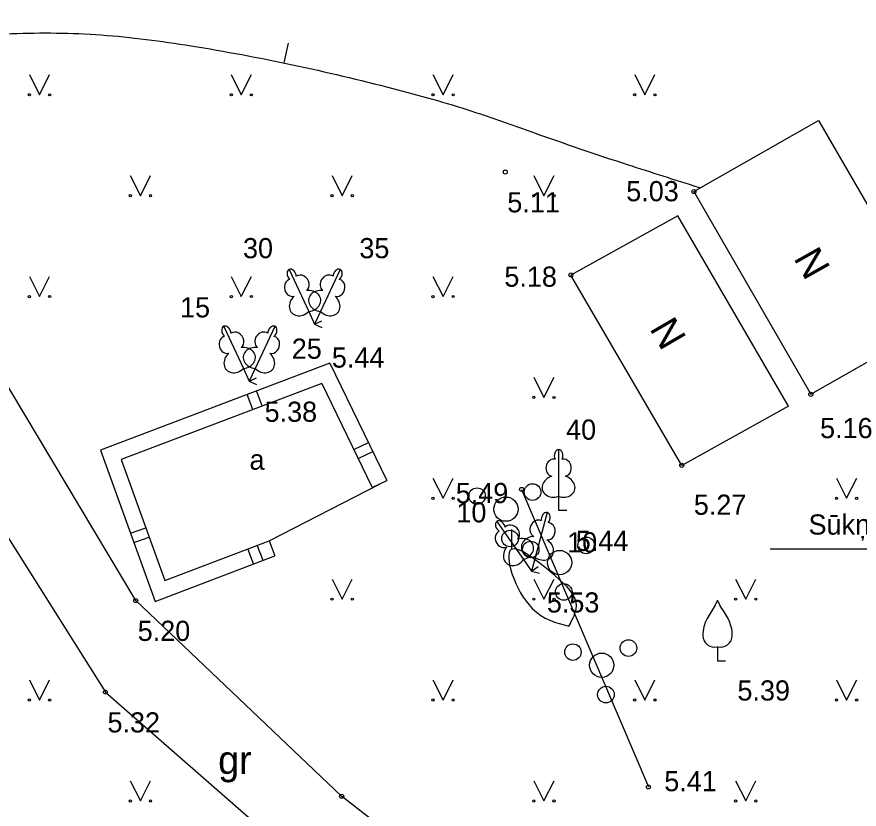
# Model space of a CAD drawing. Extents: x 519536 to 519949, y 326041 to 326519.
# Drawn here: x 519709.44 to 519730.31, y 326152.3 to 326171.93 of the extents above; entities that cross this region are included whole.
import ezdxf

# ---------------------------------------------------------------- set-up
doc = ezdxf.new("R2010")
doc.units = 0
for name, color, linetype in [('BUVE_BDET_####_####_#', 7, 'Continuous'), ('BUVE_BDET_####_TKST_#', 7, 'Continuous'), ('BUVE_EKAS_BPAL_####_#', 7, 'Continuous'), ('BUVE_EKAS_RAKS_TKST_#', 7, 'Continuous'), ('CELI_CMAL_####_####_#', 7, 'Continuous'), ('CELI_CSEG_####_TKST_#', 7, 'Continuous'), ('RELJ_AATZ_####_TKST_#', 7, 'Continuous'), ('RELJ_ELEM_####_####_#', 7, 'Continuous'), ('RELJ_HORZ_PAMT_####_#', 7, 'Continuous'), ('SKAN_ELEM_SPDK_TKST_#', 7, 'Continuous'), ('TERT_DIAM_####_TKST_#', 7, 'Continuous'), ('TERT_ELEM_####_####_#', 7, 'Continuous'), ('TERT_KRND_####_####_#', 7, 'Continuous')]:
    doc.layers.add(name, color=color, linetype=linetype)

msp = doc.modelspace()

# ---------------------------------------------------------------- linework, layer by layer
at = {"layer": 'BUVE_BDET_####_####_#'}
for p, q in [((519717.197, 326163.352), (519711.51, 326161.196)), ((519717.197, 326163.352), (519711.51, 326161.196)), ((519717.197, 326163.352), (519711.51, 326161.196)), ((519717.197, 326163.352), (519711.51, 326161.196)), ((519717.197, 326163.352), (519711.51, 326161.196)), ((519717.197, 326163.352), (519711.51, 326161.196)), ((519717.197, 326163.352), (519711.51, 326161.196)), ((519717.197, 326163.352), (519711.51, 326161.196)), ((519717.197, 326163.352), (519711.51, 326161.196)), ((519717.197, 326163.352), (519711.51, 326161.196)), ((519717.197, 326163.352), (519711.51, 326161.196)), ((519717.197, 326163.352), (519711.51, 326161.196)), ((519717.197, 326163.352), (519718.607, 326160.441)), ((519717.197, 326163.352), (519718.607, 326160.441)), ((519717.197, 326163.352), (519718.607, 326160.441)), ((519717.197, 326163.352), (519718.607, 326160.441)), ((519717.197, 326163.352), (519718.607, 326160.441)), ((519717.197, 326163.352), (519718.607, 326160.441)), ((519717.197, 326163.352), (519718.607, 326160.441)), ((519717.197, 326163.352), (519718.607, 326160.441)), ((519717.197, 326163.352), (519718.607, 326160.441)), ((519717.197, 326163.352), (519718.607, 326160.441)), ((519717.197, 326163.352), (519718.607, 326160.441)), ((519717.197, 326163.352), (519718.607, 326160.441)), ((519716.997, 326162.849), (519712.02, 326160.962)), ((519716.997, 326162.849), (519712.02, 326160.962)), ((519716.997, 326162.849), (519712.02, 326160.962)), ((519716.997, 326162.849), (519712.02, 326160.962)), ((519716.997, 326162.849), (519712.02, 326160.962)), ((519716.997, 326162.849), (519712.02, 326160.962)), ((519716.997, 326162.849), (519712.02, 326160.962)), ((519716.997, 326162.849), (519712.02, 326160.962)), ((519716.997, 326162.849), (519712.02, 326160.962)), ((519716.997, 326162.849), (519712.02, 326160.962)), ((519716.997, 326162.849), (519712.02, 326160.962)), ((519716.997, 326162.849), (519712.02, 326160.962)), ((519716.997, 326162.849), (519718.247, 326160.267)), ((519716.997, 326162.849), (519718.247, 326160.267)), ((519716.997, 326162.849), (519718.247, 326160.267)), ((519716.997, 326162.849), (519718.247, 326160.267)), ((519716.997, 326162.849), (519718.247, 326160.267)), ((519716.997, 326162.849), (519718.247, 326160.267)), ((519716.997, 326162.849), (519718.247, 326160.267)), ((519716.997, 326162.849), (519718.247, 326160.267)), ((519716.997, 326162.849), (519718.247, 326160.267)), ((519716.997, 326162.849), (519718.247, 326160.267)), ((519716.997, 326162.849), (519718.247, 326160.267)), ((519716.997, 326162.849), (519718.247, 326160.267)), ((519715.519, 326162.288), (519715.377, 326162.662)), ((519715.285, 326162.2), (519715.143, 326162.574)), ((519717.791, 326161.208), (519718.151, 326161.383)), ((519717.9, 326160.983), (519718.26, 326161.158)), ((519715.692, 326158.95), (519718.427, 326160.354)), ((519718.247, 326160.267), (519718.607, 326160.441)), ((519712.255, 326159.136), (519712.631, 326159.272)), ((519712.34, 326158.901), (519712.716, 326159.037)), ((519715.538, 326158.463), (519715.395, 326158.837)), ((519715.692, 326158.95), (519715.834, 326158.576)), ((519715.304, 326158.374), (519715.162, 326158.748))]:
    msp.add_line(p, q, dxfattribs=at)
for points in [[(519711.51, 326161.196), (519712.867, 326157.445), (519715.834, 326158.576)], [(519711.51, 326161.196), (519712.867, 326157.445), (519715.834, 326158.576)], [(519711.51, 326161.196), (519712.867, 326157.445), (519715.834, 326158.576)], [(519711.51, 326161.196), (519712.867, 326157.445), (519715.834, 326158.576)], [(519711.51, 326161.196), (519712.867, 326157.445), (519715.834, 326158.576)], [(519711.51, 326161.196), (519712.867, 326157.445), (519715.834, 326158.576)], [(519711.51, 326161.196), (519712.867, 326157.445), (519715.834, 326158.576)], [(519711.51, 326161.196), (519712.867, 326157.445), (519715.834, 326158.576)], [(519711.51, 326161.196), (519712.867, 326157.445), (519715.834, 326158.576)], [(519711.51, 326161.196), (519712.867, 326157.445), (519715.834, 326158.576)], [(519711.51, 326161.196), (519712.867, 326157.445), (519715.834, 326158.576)], [(519711.51, 326161.196), (519712.867, 326157.445), (519715.834, 326158.576)], [(519712.02, 326160.962), (519713.105, 326157.963), (519715.692, 326158.95)], [(519712.02, 326160.962), (519713.105, 326157.963), (519715.692, 326158.95)], [(519712.02, 326160.962), (519713.105, 326157.963), (519715.692, 326158.95)], [(519712.02, 326160.962), (519713.105, 326157.963), (519715.692, 326158.95)], [(519712.02, 326160.962), (519713.105, 326157.963), (519715.692, 326158.95)], [(519712.02, 326160.962), (519713.105, 326157.963), (519715.692, 326158.95)], [(519712.02, 326160.962), (519713.105, 326157.963), (519715.692, 326158.95)], [(519712.02, 326160.962), (519713.105, 326157.963), (519715.692, 326158.95)], [(519712.02, 326160.962), (519713.105, 326157.963), (519715.692, 326158.95)], [(519712.02, 326160.962), (519713.105, 326157.963), (519715.692, 326158.95)], [(519712.02, 326160.962), (519713.105, 326157.963), (519715.692, 326158.95)], [(519712.02, 326160.962), (519713.105, 326157.963), (519715.692, 326158.95)]]:
    msp.add_lwpolyline(points, dxfattribs=at)
at = {"layer": 'BUVE_EKAS_BPAL_####_#'}
for p, q in [((519726.216, 326167.601), (519729.306, 326169.364)), ((519729.306, 326169.364), (519732.203, 326164.34)), ((519726.216, 326167.601), (519729.113, 326162.577)), ((519725.815, 326166.999), (519723.169, 326165.534)), ((519728.561, 326162.282), (519725.815, 326166.999)), ((519725.915, 326160.817), (519723.169, 326165.534)), ((519729.113, 326162.577), (519732.203, 326164.34)), ((519728.561, 326162.282), (519725.915, 326160.817))]:
    msp.add_line(p, q, dxfattribs=at)
at = {"layer": 'CELI_CMAL_####_####_#'}
for points in [[(519725.6, 326145.595), (519722.795, 326148.479), (519717.487, 326152.615), (519712.383, 326157.466), (519706.872, 326166.697), (519703.889, 326170.776), (519699.04, 326175.245), (519687.684, 326181.825), (519678.238, 326187.413), (519670.804, 326192.027), (519670.048, 326192.682), (519664.865, 326189.411), (519662.65, 326188.197)], [(519662.737, 326185.995), (519665.714, 326187.6), (519670.496, 326188.216), (519674.588, 326187.052), (519687.563, 326179.623), (519697.361, 326173.852), (519702.298, 326169.28), (519707.151, 326162.302), (519711.634, 326155.197), (519719.91, 326147.956), (519722.688, 326145.028)]]:
    msp.add_lwpolyline(points, dxfattribs=at)
at = {"layer": 'RELJ_ELEM_####_####_#'}
for centre in [(519721.542, 326168.086), (519726.216, 326167.601), (519723.169, 326165.534), (519729.113, 326162.577), (519725.915, 326160.817), (519721.946, 326160.222), (519712.383, 326157.466), (519711.634, 326155.197), (519725.089, 326152.848), (519717.487, 326152.615)]:
    msp.add_circle(centre, 0.05, dxfattribs=at)
at = {"layer": 'RELJ_HORZ_PAMT_####_#'}
for p, q in [((519716.158, 326171.278), (519716.058, 326170.789)), ((519721.702, 326158.729), (519721.702, 326159.229))]:
    msp.add_line(p, q, dxfattribs=at)
for points in [[(519703.7, 326170.95), (519704.708, 326171.096), (519707.058, 326171.344), (519709.307, 326171.516), (519711.53, 326171.484), (519712.642, 326171.373), (519713.753, 326171.213), (519716.272, 326170.744), (519718.755, 326170.156), (519720.711, 326169.596), (519722.223, 326169.07), (519724.566, 326168.272), (519726.32, 326167.713), (519726.38, 326167.694)], [(519723.12, 326156.833), (519722.208, 326157.271), (519721.691, 326158.729), (519722.766, 326158.087), (519723.306, 326157.331), (519723.12, 326156.833)]]:
    msp.add_spline(points, degree=3, dxfattribs=at)
at = {"layer": 'SKAN_ELEM_SPDK_TKST_#'}
msp.add_lwpolyline([(519728.103, 326158.751), (519734.072, 326158.751), (519735.575, 326155.913)], dxfattribs=at)
at = {"layer": 'TERT_ELEM_####_####_#'}
for p, q in [((519709.75, 326170.5), (519710, 326170)), ((519710, 326170), (519710.25, 326170.5)), ((519714.75, 326170.5), (519715, 326170)), ((519715, 326170), (519715.25, 326170.5)), ((519719.75, 326170.5), (519720, 326170)), ((519720, 326170), (519720.25, 326170.5)), ((519724.75, 326170.5), (519725, 326170)), ((519725, 326170), (519725.25, 326170.5)), ((519712.25, 326168), (519712.5, 326167.5)), ((519712.5, 326167.5), (519712.75, 326168)), ((519717.25, 326168), (519717.5, 326167.5)), ((519717.5, 326167.5), (519717.75, 326168)), ((519722.25, 326168), (519722.5, 326167.5)), ((519722.5, 326167.5), (519722.75, 326168)), ((519709.75, 326165.5), (519710, 326165)), ((519710, 326165), (519710.25, 326165.5)), ((519714.75, 326165.5), (519715, 326165)), ((519715, 326165), (519715.25, 326165.5)), ((519719.75, 326165.5), (519720, 326165)), ((519720, 326165), (519720.25, 326165.5)), ((519716.671, 326164.629), (519716.818, 326164.315)), ((519716.965, 326164.629), (519716.818, 326164.315)), ((519716.818, 326164.315), (519716.999, 326164.4)), ((519716.818, 326164.315), (519716.999, 326164.23)), ((519715.052, 326163.217), (519715.199, 326162.903)), ((519715.346, 326163.217), (519715.199, 326162.903)), ((519722.25, 326163), (519722.5, 326162.5)), ((519722.5, 326162.5), (519722.75, 326163)), ((519715.199, 326162.903), (519715.38, 326162.988)), ((519715.199, 326162.903), (519715.38, 326162.818)), ((519719.75, 326160.5), (519720, 326160)), ((519720, 326160), (519720.25, 326160.5)), ((519729.75, 326160.5), (519730, 326160)), ((519730, 326160), (519730.25, 326160.5)), ((519722.863, 326160.05), (519722.863, 326159.703)), ((519722.863, 326159.703), (519723.063, 326159.703)), ((519721.995, 326158.482), (519722.194, 326158.198)), ((519722.284, 326158.533), (519722.194, 326158.198)), ((519722.194, 326158.198), (519722.358, 326158.313)), ((519722.194, 326158.198), (519722.387, 326158.146)), ((519717.25, 326158), (519717.5, 326157.5)), ((519717.5, 326157.5), (519717.75, 326158)), ((519722.25, 326158), (519722.5, 326157.5)), ((519722.5, 326157.5), (519722.75, 326158)), ((519727.25, 326158), (519727.5, 326157.5)), ((519727.5, 326157.5), (519727.75, 326158)), ((519726.801, 326156.324), (519726.801, 326155.972)), ((519726.801, 326155.972), (519727.001, 326155.972)), ((519709.75, 326155.5), (519710, 326155)), ((519710, 326155), (519710.25, 326155.5)), ((519719.75, 326155.5), (519720, 326155)), ((519720, 326155), (519720.25, 326155.5)), ((519724.75, 326155.5), (519725, 326155)), ((519725, 326155), (519725.25, 326155.5)), ((519729.75, 326155.5), (519730, 326155)), ((519730, 326155), (519730.25, 326155.5)), ((519712.25, 326153), (519712.5, 326152.5)), ((519712.5, 326152.5), (519712.75, 326153)), ((519722.25, 326153), (519722.5, 326152.5)), ((519722.5, 326152.5), (519722.75, 326153)), ((519727.25, 326153), (519727.5, 326152.5)), ((519727.5, 326152.5), (519727.75, 326153))]:
    msp.add_line(p, q, dxfattribs=at)
for points in [[(519716.184, 326165.674), (519716.671, 326164.629)], [(519716.363, 326165.502), (519716.362, 326165.502)], [(519717.452, 326165.674), (519716.965, 326164.629)], [(519717.435, 326165.426), (519717.434, 326165.427)], [(519714.565, 326164.262), (519715.052, 326163.217)], [(519715.833, 326164.262), (519715.346, 326163.217)], [(519714.744, 326164.09), (519714.743, 326164.09)], [(519715.816, 326164.014), (519715.815, 326164.015)], [(519722.863, 326161.203), (519722.863, 326160.05)], [(519722.953, 326160.971), (519722.952, 326160.972)], [(519722.582, 326159.647), (519722.284, 326158.533)], [(519721.334, 326159.427), (519721.995, 326158.482)], [(519721.54, 326159.288), (519721.539, 326159.288)], [(519722.609, 326159.399), (519722.608, 326159.4)]]:
    msp.add_lwpolyline(points, dxfattribs=at)
for centre, radius in [((519709.75, 326170), 0.028), ((519710.25, 326170), 0.0263), ((519714.75, 326170), 0.028), ((519715.25, 326170), 0.0263), ((519719.75, 326170), 0.028), ((519720.25, 326170), 0.0263), ((519724.75, 326170), 0.028), ((519725.25, 326170), 0.0263), ((519712.25, 326167.5), 0.028), ((519712.75, 326167.5), 0.0263), ((519717.25, 326167.5), 0.028), ((519717.75, 326167.5), 0.0263), ((519722.25, 326167.5), 0.028), ((519722.75, 326167.5), 0.0263), ((519709.75, 326165), 0.028), ((519710.25, 326165), 0.0263), ((519714.75, 326165), 0.028), ((519715.25, 326165), 0.0263), ((519719.75, 326165), 0.028), ((519720.25, 326165), 0.0263), ((519722.25, 326162.5), 0.028), ((519722.75, 326162.5), 0.0263), ((519722.218, 326160.156), 0.207), ((519720.843, 326160.055), 0.204), ((519719.75, 326160), 0.028), ((519720.25, 326160), 0.0263), ((519721.557, 326159.731), 0.301), ((519729.75, 326160), 0.028), ((519730.25, 326160), 0.0263), ((519721.66, 326159.003), 0.205), ((519723.548, 326158.833), 0.207), ((519722.173, 326158.732), 0.204), ((519722.887, 326158.408), 0.301), ((519722.99, 326157.68), 0.205), ((519717.25, 326157.5), 0.028), ((519717.75, 326157.5), 0.0263), ((519722.25, 326157.5), 0.028), ((519722.75, 326157.5), 0.0263), ((519727.25, 326157.5), 0.028), ((519727.75, 326157.5), 0.0263), ((519723.218, 326156.188), 0.204), ((519724.593, 326156.289), 0.207), ((519723.932, 326155.864), 0.301), ((519724.035, 326155.136), 0.205), ((519709.75, 326155), 0.028), ((519710.25, 326155), 0.0263), ((519719.75, 326155), 0.028), ((519720.25, 326155), 0.0263), ((519724.75, 326155), 0.028), ((519725.25, 326155), 0.0263), ((519729.75, 326155), 0.028), ((519730.25, 326155), 0.0263), ((519712.25, 326152.5), 0.028), ((519712.75, 326152.5), 0.0263), ((519722.25, 326152.5), 0.028), ((519722.75, 326152.5), 0.0263), ((519727.25, 326152.5), 0.028), ((519727.75, 326152.5), 0.0263)]:
    msp.add_circle(centre, radius, dxfattribs=at)
for centre, radius, start, end in [((519726.384, 326157.61), 0.439, 324.3837, 341.712), ((519727.218, 326157.61), 0.439, 198.288, 215.6163), ((519739.426, 326149.576), 14.88, 148.4844, 149.9901), ((519714.176, 326149.576), 14.88, 30.0099, 31.5156), ((519727.325, 326156.597), 0.89, 151.757, 179.9138), ((519726.277, 326156.597), 0.89, 0.0862, 28.243), ((519726.725, 326156.603), 0.29, 181.0782, 285.2823), ((519726.877, 326156.603), 0.29, 254.7177, 358.9218)]:
    msp.add_arc(centre, radius, start, end, dxfattribs=at)
for centre, major_axis, ratio, start_param, end_param in [((519716.248, 326165.539), (0.063, -0.136), 0.707107, 3.14537, 5.287485), ((519716.247, 326165.538), (0.063, -0.136), 0.707107, 0.995701, 3.137816), ((519716.488, 326165.326), (0.125, -0.176), 0.861323, 0, 3.141593), ((519717.148, 326165.326), (-0.125, -0.176), 0.861323, 3.141593, 6.283185), ((519717.389, 326165.538), (-0.063, -0.136), 0.707107, 3.14537, 5.287485), ((519717.388, 326165.539), (-0.063, -0.136), 0.707107, 0.995701, 3.137816), ((519716.256, 326165.217), (0.055, -0.209), 0.861323, 3.141593, 6.283185), ((519717.38, 326165.217), (-0.055, -0.209), 0.861323, 0, 3.141593), ((519716.649, 326164.89), (-0.318, -0.043), 0.814445, 1.531171, 4.712389), ((519716.987, 326164.89), (0.318, -0.043), 0.814445, 1.570796, 4.752015), ((519716.486, 326164.815), (0.238, 0.216), 0.814445, 1.570796, 4.752015), ((519717.15, 326164.815), (-0.238, 0.216), 0.814445, 1.531171, 4.712389), ((519714.629, 326164.127), (0.063, -0.136), 0.707107, 3.14537, 5.287485), ((519714.628, 326164.126), (0.063, -0.136), 0.707107, 0.995701, 3.137816), ((519715.77, 326164.126), (-0.063, -0.136), 0.707107, 3.14537, 5.287485), ((519715.769, 326164.127), (-0.063, -0.136), 0.707107, 0.995701, 3.137816), ((519714.869, 326163.914), (0.125, -0.176), 0.861323, 0, 3.141593), ((519715.529, 326163.914), (-0.125, -0.176), 0.861323, 3.141593, 6.283185), ((519714.637, 326163.805), (0.055, -0.209), 0.861323, 3.141593, 6.283185), ((519715.761, 326163.805), (-0.055, -0.209), 0.861323, 0, 3.141593), ((519715.03, 326163.478), (-0.318, -0.043), 0.814445, 1.531171, 4.712389), ((519715.368, 326163.478), (0.318, -0.043), 0.814445, 1.570796, 4.752015), ((519714.867, 326163.403), (0.238, 0.216), 0.814445, 1.570796, 4.752015), ((519715.531, 326163.403), (-0.238, 0.216), 0.814445, 1.531171, 4.712389), ((519722.863, 326161.053), (0, -0.15), 0.707107, 3.14537, 5.287485), ((519722.863, 326161.053), (0, -0.15), 0.707107, 0.995701, 3.137816), ((519722.735, 326160.758), (-0.039, -0.212), 0.861323, 3.141593, 6.283185), ((519722.991, 326160.758), (0.039, -0.212), 0.861323, 0, 3.141593), ((519722.773, 326160.296), (0.307, 0.095), 0.814445, 1.570796, 4.752015), ((519722.953, 326160.296), (-0.307, 0.095), 0.814445, 1.531171, 4.712389), ((519722.544, 326159.502), (-0.039, -0.145), 0.707107, 3.14537, 5.287485), ((519721.419, 326159.304), (0.086, -0.123), 0.707107, 0.995701, 3.137816), ((519722.343, 326159.25), (-0.092, -0.195), 0.861323, 3.141593, 6.283185), ((519722.543, 326159.502), (-0.039, -0.145), 0.707107, 0.995701, 3.137816), ((519721.42, 326159.304), (0.086, -0.123), 0.707107, 3.14537, 5.287485), ((519721.694, 326159.136), (0.154, -0.152), 0.861323, 0, 3.141593), ((519722.591, 326159.184), (-0.018, -0.215), 0.861323, 6.283185, 9.424778), ((519721.484, 326158.989), (0.09, -0.196), 0.861323, 3.141593, 6.283185), ((519722.261, 326158.794), (0.321, 0.012), 0.814445, 1.570796, 4.752015), ((519721.927, 326158.735), (-0.306, -0.098), 0.814445, 1.531171, 4.712389), ((519722.434, 326158.748), (-0.272, 0.171), 0.814445, 1.531171, 4.712389), ((519721.781, 326158.632), (0.197, 0.254), 0.814445, 1.570796, 4.752015)]:
    msp.add_ellipse(centre, major_axis=major_axis, ratio=ratio, start_param=start_param, end_param=end_param, dxfattribs=at)
at = {"layer": 'TERT_KRND_####_####_#'}
msp.add_lwpolyline([(519721.946, 326160.222), (519725.089, 326152.848)], dxfattribs=at)

# ---------------------------------------------------------------- texts
at = {"layer": 'BUVE_BDET_####_TKST_#'}
msp.add_text('a', height=0.5, dxfattribs=at).set_placement((519715.204, 326160.708))
at = {"layer": 'BUVE_EKAS_RAKS_TKST_#'}
for rotation, p in [(299.3697, (519728.675, 326165.953)), (300.2058, (519725.104, 326164.207))]:
    msp.add_text('N', height=0.7, rotation=rotation, dxfattribs=at).set_placement(p)
at = {"layer": 'CELI_CSEG_####_TKST_#'}
msp.add_text('gr', height=0.7, dxfattribs=at).set_placement((519714.427, 326153.167))
at = {"layer": 'RELJ_AATZ_####_TKST_#'}
for s, p in [('5.03', (519724.539, 326167.362)), ('5.11', (519721.592, 326167.086)), ('5.18', (519721.519, 326165.244)), ('5.44', (519717.244, 326163.239)), ('5.38', (519715.578, 326161.896)), ('5.16', (519729.342, 326161.491)), ('5.49', (519720.315, 326159.881)), ('5.27', (519726.214, 326159.592)), ('5.44', (519723.289, 326158.696)), ('5.53', (519722.572, 326157.169)), ('5.20', (519712.433, 326156.466)), ('5.39', (519727.295, 326154.988)), ('5.32', (519711.684, 326154.197)), ('5.41', (519725.482, 326152.741))]:
    msp.add_text(s, height=0.5, dxfattribs=at).set_placement(p)
at = {"layer": 'SKAN_ELEM_SPDK_TKST_#'}
msp.add_text('Sūkņu stacija', height=0.5, dxfattribs=at).set_placement((519729.056, 326159.101))
at = {"layer": 'TERT_DIAM_####_TKST_#'}
for s, p in [('30', (519715.042, 326165.95)), ('35', (519717.926, 326165.95)), ('15', (519713.483, 326164.483)), ('25', (519716.251, 326163.459)), (' 40', (519722.863, 326161.453)), ('10', (519720.33, 326159.404)), ('10', (519723.075, 326158.659))]:
    msp.add_text(s, height=0.5, dxfattribs=at).set_placement(p)

doc.saveas('drawing.dxf')
